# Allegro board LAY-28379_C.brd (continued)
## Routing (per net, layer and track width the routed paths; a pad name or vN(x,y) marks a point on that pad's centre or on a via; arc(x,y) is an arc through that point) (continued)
P3V3: length 201.8
  TOP w0.254: R26.1 63.41,36.7 63.41,36.21 63.41,36.2 v1(63.41,35.98)
  TOP w0.305: U12.1 v1(39.08,31.97) ; U12.8 v1(43.57,34.09)
  TOP w0.381: 23.77,18.45 J18.2 24.71,17.51 ; 28.41,6.81 C48.1 ; C48.1 29.05,7.57 ; C48.1 28.41,8.33 ; 34.51,2.57 J3.8 ; J3.8 35.52,3.58 ; J3.8 36.54,2.57 ; 29.43,2.57 J3.4 ; J3.4 30.44,3.58 ; J3.4 31.46,2.57 ; 18.84,9.84 J15.1 17.9,10.78
  TOP w0.508: v1(16.6,42.95) 18.81,42.95 19.63,43.77 23.35,43.77 SH3.1 24.79,44.63 v1(25.19,45.03) ; R17.1 v1(60.95,39.75)
  TOP w0.635: v1(51.88,7.44) R78.1 ; J20.1 22.88,9.84 23.13,10.08 24.02,10.08
  INT_1 w0.508: v1(25.19,45.03) 25.64,44.58 25.74,44.58 25.79,44.53 28.39,44.53 29.43,43.49 29.43,42.92 30.23,42.13 32.62,42.13 32.66,42.16 v1(33.29,42.16)
  INT_1 w0.635: v1(10.67,40.36) 10.67,38.82 12,37.49 v1(12,23.47)
  BOTTOM w0.152: TP534.1 v1(29.6,9.42)
  BOTTOM w0.254: v1(33.29,42.16) 32.89,41.76 SH500.2
  BOTTOM w0.508: J9.1 38.44,29.72 39.1,30.38 39.1,31.94 v1(39.08,31.97) 40.81,31.97 42.94,34.09 v1(43.57,34.09) 43.57,34.87 C510.1 ; v1(16.6,42.95) 16.07,43.48 14.01,43.48 12.08,41.55 SH502.2 ; v1(12,23.47) 12.51,22.96 20.83,22.96 23.7,20.09 J18.2 ; R509.1 60.28,24.26 R508.1 ; v1(63.41,35.98) 63.41,37 61.61,38.81 61.61,39.09 v1(60.95,39.75) 59.7,38.51 52.39,38.51 51.13,39.77 v1(48.04,39.77) 48.04,42.92 45.21,45.74 34.82,45.74 33.7,46.86 29.38,46.86 27.55,45.03 v1(25.19,45.03)
  BOTTOM w0.635: SH502.2 11.25,39.78 v1(10.67,40.36) ; v1(51.88,7.44) 51.18,7.44 50.83,7.09 v1(30.49,7.09) SH503.2 ; J21.1 20.84,7.92 21.6,8.69 22.11,8.69 22.86,9.44 J20.1 ; v1(48.04,39.77) 46.75,38.48 46.75,36.75 44.55,34.55 44.55,34.46 44.18,34.09 v1(43.57,34.09) 43.57,33.55 44.28,32.84 44.28,32.03 44.64,31.67 J8.1 47.58,30.9 49.45,30.9 50.94,32.38 57.59,32.38 60.32,29.66 R508.1
P3V3_BATT: length 31.8
  TOP w0.508: C43.1 10.57,18.4 ; C43.1 9.94,19.16 ; C43.1 9.94,17.64 ; 16.64,14.57 J27.2 ; J27.2 15.7,15.51 ; J27.2 16.64,16.45 ; 9.92,15.75 11.35,15.75 ; 9.92,15.75 9.92,14.31 ; 9.92,15.75 9.92,17.18 ; 9.92,15.75 8.48,15.75
  INT_1 w0.762: 9.92,15.75 BT500.1
P3V3_BRD: length 79.6
  TOP w0.254: U9.14 v1(50.39,36.34) ; v1(52.87,31.12) 53.42,31.66 U9.1
  TOP w0.508: U4.6 R22.2 C6.1 45.89,39.78 v1(45.97,39.69) 46.78,39.69 48.17,38.3 v1(48.17,37.24) ; v1(59.5,34.32) 60.13,34.32 R29.1 ; R513.1 55.08,43.08 v1(55.64,43.64) 55,43.64 54.99,43.62 54.38,43.62 R13.1 R510.1
  TOP w0.635: R20.1 34.12,39.42 v1(33.52,39.42) ; R20.1 33.79,40.46 R16.1 ; R20.1 R24.1
  INT_1 w0.508: J8.2 47.28,33.67 48.45,34.85 48.45,35.65 49.38,36.58 50.15,36.58 v1(50.39,36.34) 51.04,35.69 51.04,33.86 52.87,32.03 v1(52.87,31.12) ; v1(59.5,34.32) 58.28,34.32 57.77,34.82 57.77,42.14 56.27,43.64 v1(55.64,43.64)
  BOTTOM w0.508: v1(59.5,34.32) 58.64,33.45 53.28,33.45 v1(50.39,36.34) 50.39,37.43 C507.1 C508.1 48.86,37.24 v1(48.17,37.24) ; R507.1 C519.1 50.08,28.6 51.35,29.87 51.35,30.33 52.13,31.12 v1(52.87,31.12)
  BOTTOM w0.635: v1(33.52,39.42) 34.32,38.62 44.9,38.62 v1(45.97,39.69)
P3V3_LED: length 105.5
  TOP w0.508: v1(63.76,10.01) 63.76,10.48 63.09,11.15 LED5.A ; v1(25.29,5.51) 24.09,5.51 R82.1
  TOP w0.635: v1(25.29,5.51) 26.05,5.51 26.38,5.84 v1(26.38,6.53) 25.92,6.53 TP544.1 ; v1(61.25,23.29) LED4.A LED3.A LED2.A LED1.A
  INT_1 w0.508: v1(41.91,23.24) 41.91,19.42 43.73,17.6 43.73,15.39 49.37,9.75 v1(50.19,9.75) ; v1(63.76,10.01) 63.76,9.14 63.28,8.66 63.28,7.24 62.69,6.65 v1(54.02,6.65)
  INT_1 w0.635: v1(26.38,6.53) 27.08,6.53 27.33,6.27 52.94,6.27 53.32,6.65 v1(54.02,6.65)
  BOTTOM w0.381: C49.1 v1(25.29,5.51)
  BOTTOM w0.508: v1(50.19,9.75) 51.81,9.75 54.02,7.54 v1(54.02,6.65) ; v1(41.91,23.24) 42.76,24.09 46.38,24.09 47.64,25.35 50.23,25.35 51.01,26.12 55.73,26.12 57.74,24.1 57.74,22.11 58.6,21.26 60.79,21.26 61.25,21.72 v1(61.25,23.29)
  BOTTOM w0.635: SH503.1 26.94,7.09 v1(26.38,6.53)
P3V3_LED_PWR: length 4.5
  TOP w0.635: LED6.A v1(19.25,7.39)
  BOTTOM w0.635: J20.2 20.09,9.84 19.25,9 v1(19.25,7.39)
P3V3_SDA: length 143.3
  TOP w0.305: v1(15.99,36.93) 16.34,36.93 16.62,37.2 U7.7 ; U8.7 29.33,35.62 v1(29.17,35.46) ; U14.1 v1(29.41,29.77) ; U11.5 23.08,34.03 ; U7.11 v1(18.72,35.22) ; U13.1 v1(29.31,32.69) ; U16.1 v1(29.59,23.44) ; U7.1 v1(17.07,40.86) ; U15.1 v1(29.47,26.57) ; v1(28.94,40.82) 29.27,40.82 29.57,40.52 U5.1
  TOP w0.381: 23.08,34.03 v1(23.05,34.05)
  TOP w0.508: R33.1 v1(16.68,34.34) ; R59.1 v1(32.19,26.44) ; R34.2 v1(24.65,34.14) ; R38.1 20.51,31.42 v1(20.46,31.47) ; R37.1 v1(32.04,32.56) ; J11.1 C31.1 26.53,22.05 27.93,23.44 v1(29.59,23.44) ; R49.1 v1(32.14,29.64) ; R64.1 v1(32.37,23.32) ; R63.1 v1(21.02,25.58) ; v1(17.07,40.86) 17.09,40.88 17.09,41.28 15.59,42.77 v1(11.82,42.77) ; v1(28.94,40.82) 26.88,42.88 R10.1 ; 29.27,40.82 29.68,40.82 30.07,41.21 30.88,41.21 31.48,40.61 R19.1 v1(32.37,40.41)
  INT_1 w0.508: v1(32.37,40.41) 32.37,39.5 32.04,39.17 v1(32.04,32.56) ; v1(11.82,42.77) 10.9,41.85 7.62,41.85 5.55,43.92 v1(5.55,46.38) ; v1(32.14,29.64) 32.14,26.49 v1(32.19,26.44) 32.19,23.5 v1(32.37,23.32) ; v1(15.99,36.93) 17.07,38.01 v1(17.07,40.86) ; v1(21.02,25.58) 21.02,30.91 v1(20.46,31.47) ; v1(29.59,23.44) 29.47,23.57 v1(29.47,26.57) 29.47,29.72 v1(29.41,29.77) 29.31,29.87 v1(29.31,32.69) 29.17,32.83 v1(29.17,35.46) 29.17,38.28 29.57,38.67 29.57,40.52 29.27,40.82 v1(28.94,40.82) ; v1(23.05,34.05) 23.93,34.05 24.02,34.14 v1(24.65,34.14) ; v1(7.58,48.46) 7.58,48.11 5.85,46.38 v1(5.55,46.38) ; v1(5.55,46.38) v1(3.8,48.13)
  BOTTOM w0.203: v1(7.58,48.46) 7.27,48.78 U500.1
  BOTTOM w0.508: SH501.1 13.45,40.44 13.96,40.94 C502.1 14.9,40.92 C504.1 17.01,40.92 v1(17.07,40.86) 17.82,40.11 28.23,40.11 v1(28.94,40.82) 29.56,40.2 C505.1 ; C521.1 29.47,27.24 v1(29.47,26.57) ; v1(29.31,32.69) 29.31,33.36 C516.1 ; 8.39,48.46 v1(7.58,48.46) ; v1(29.59,23.44) 29.59,24.12 C523.1 ; R503.1 5.91,46.74 v1(5.55,46.38) ; C518.1 29.39,29.74 v1(29.41,29.77) ; v1(29.17,35.46) C514.1 ; C513.1 23.08,34.08 v1(23.05,34.05) 21.18,34.05 20.97,34.26 19.37,34.26 18.72,34.91 v1(18.72,35.22) 18.72,35.88 C509.1 v1(15.99,36.93) 15.99,35.03 v1(16.68,34.34) 19.55,31.47 v1(20.46,31.47) ; R501.2 v1(3.8,48.13) ; v1(32.04,32.56) 32.04,32.21 32.75,31.5 32.75,30.25 v1(32.14,29.64)
P3V3_VREG: length 14.8
  TOP w0.508: 13.11,20.12 D7.A ; D7.A 12.46,21.01 ; D7.A 13.76,21.01 ; D7.A 13.11,21.9 ; U17.2 4.79,22.79 ; U17.2 4,24.08 ; U17.2 4,21.49 ; U17.2 3.21,22.79 ; U17.4 4,17.88 ; U17.4 1.94,16.58 ; U17.4 6.06,16.58 ; 8.35,21.68 C27.1 ; C27.1 9.12,21.05 ; C27.1 9.88,21.68
P5V0_SDA_USB_CONN_VBUS: length 5.5
  TOP w0.406: J6.1 5.59,40.97 U6.1
  TOP w0.508: L1.1 8.18,39.42 v1(8.17,39.44) U6.1
P5V_LDO_OUT: length 7.3
  TOP w0.508: 3.5,3.48 J26.3 ; J26.3 4.46,2.53 ; J26.3 4.46,4.43 ; 3.53,5.37 D10.A ; D10.A 4.42,6.02 ; D10.A 3.53,6.66 ; D10.A 2.64,6.02 ; 1.47,5.38 C53.1 2.24,6.01
P5V_SDA: length 35.1
  TOP w0.152: C13.1 12.46,36.86 ; C13.1 11.82,36.09 ; C13.1 12.46,35.33 ; 11.91,34.4 U10.1 12.71,34.9 ; 10.76,34.47 C21.1 ; C21.1 11.26,34.98 ; C21.1 11.77,34.47 ; 11.19,31.06 R40.1 11.7,30.56
  TOP w0.254: 16.27,37.49 16.48,37.71 U7.6
  TOP w0.305: 16.27,37.49 15.1,37.49 v1(14.95,37.34)
  TOP w0.508: L1.2 C3.1 11.75,38.79 ; v1(14.95,37.34) 14.91,37.34 14.63,37.62 12.93,37.62 ; v1(17.26,44.48) 17.23,44.48 16.4,43.64 v1(13.19,43.64) ; R46.1 v1(20.28,30.48)
  INT_1 w0.508: v1(13.19,43.64) 13.19,42.71 14.95,40.95 v1(14.95,37.34)
  BOTTOM w0.508: v1(20.28,30.48) v1(10.78,30.48) ; R504.1 v1(17.26,44.48)
P5V_SDA_PSW: length 11.7
  TOP w0.508: U10.6 v1(15.21,35.26)
  TOP w0.635: D3.A 6.51,34.39 D4.A v1(9.03,34.36)
  BOTTOM w0.635: v1(15.21,35.26) 14.31,34.36 v1(9.03,34.36)
P5V_USB: length 112.5
  TOP w0.254: U12.14 v1(40.12,34.08)
  TOP w0.508: 6.03,31.81 D4.C 6.92,30.52 ; D5.A 5.38,31.45 ; D5.A 4.74,30.56 ; D5.A 4.74,32.33 ; D10.C v1(3.53,10.1)
  INT_1 w0.635: v1(3.53,10.1) 3.53,12.81 5.73,15.01 v1(5.73,30.51)
  BOTTOM w0.508: v1(3.53,10.1) 3.53,7.47 4.6,6.4 18.08,6.4 23.56,0.91 36.41,0.91 J3.10 ; v1(5.73,30.51) 6.67,29.57 11.7,29.57 12.71,28.55 20.26,28.55 21.38,29.67 24.55,29.67 26.56,31.67 26.56,35.34 27.06,35.85 28.63,35.85 30.95,38.18 31.97,38.18 33.92,36.22 39.45,36.22 40.12,35.55 C512.1 40.12,34.09 v1(40.12,34.08)
VDD_1P8: length 14.7
  TOP w0.279: 47.95,19.16 46.73,17.95 46.26,17.95 46.25,17.96 46.04,17.96
  TOP w0.508: 46.04,17.96 v1(44.56,17.96)
  INT_1 w0.635: v1(38.95,14.76) 38.95,13.46 38.05,12.56 J22.5
  BOTTOM w0.635: v1(38.95,14.76) 40.3,14.76 42.99,17.45 44.05,17.45 v1(44.56,17.96)
VDD_1P8F: length 12.9
  TOP w0.279: U18.27 52.69,16.68 v1(52.69,16.99) 52.7,17 53.09,17 53.39,16.7 U18.28
  TOP w0.635: L5.2 C55.1 44.89,17.2 v1(45.2,16.89)
  INT_1 w0.508: v1(45.2,16.89) 45.91,16.89 47.03,18.01 48.81,18.01 50.05,16.76 51.83,16.76 52.06,16.99 v1(52.69,16.99)
VDD_1P45: length 9.9
  TOP w0.279: U18.15 46.61,17.12 46.52,17.12
  TOP w0.508: v1(45.13,15.73) 46.52,17.12
  TOP w0.635: v1(42.66,14.73) 42.47,14.73 41.69,13.96 C45.1 L6.1
  BOTTOM w0.635: v1(45.13,15.73) 44.13,14.73 v1(42.66,14.73)
VDD_1P45F: length 38.1
  TOP w0.254: U18.32 54.18,18.73 54.18,19.16 v1(54.47,19.45) 54.58,19.56 55.47,19.56 U18.35 ; v1(53.63,18.58) U18.31
  TOP w0.635: v1(41.36,11.3) 41.69,11.63 C54.1 41.69,12.42 42.05,12.78 L6.2
  INT_1 w0.635: J22.4 35.83,9.45 37.93,9.45 38.87,10.39 40.7,10.39 41.36,11.05 v1(41.36,11.3)
  BOTTOM w0.254: 53.33,18.73 C527.1 ; C527.1 53.83,19.23 ; C527.1 53.75,18.81 ; C527.1 53.75,19.66 ; 53.84,19.8 C526.1 ; C526.1 54.69,19.8 ; C526.1 54.26,19.71 ; 53.13,18.52 C525.1 53.04,18.09
  BOTTOM w0.635: 53.18,17.95 53.56,17.57 53.56,13.3 52.85,12.6 50.84,12.6 50.15,11.91 47.92,11.91 47.69,12.14 42.2,12.14 v1(41.36,11.3)
ADC0_SE0/BATTERY_MONITORING: length 7.3
  TOP w0.152: SH26.1 R78.2 50.86,11.24 v1(50.79,11.31) 50.46,11.64 50.46,14.61 U18.24
ADC0_SE1/POT: length 68.1
  TOP w0.152: v1(8.62,8.13) 8.3,8.45 8.3,9.74 C32.1 7.7,10.34 5.85,10.34 ; SH27.1 v1(53.38,9.68) 53.38,9.95 51.49,11.84 51.49,14.78 U18.25
  INT_1 w0.152: v1(53.38,9.68) 53.7,9.35 53.81,9.35 54.62,8.55 56.46,8.55 56.76,8.25 56.76,7.7 56.53,7.47 53.58,7.47 52.84,8.2 51.45,8.2 50.15,6.91 31.51,6.91 30.87,7.54 24.27,7.54 23.25,6.53 21.73,6.53 21.48,6.78 9.97,6.78 v1(8.62,8.13)
  BOTTOM w0.152: TP532.1 53.38,9.68 v1(53.38,9.68)
BUZZER: length 32.3
  TOP w0.152: v1(44.48,30.81) 44.48,28.56 43.9,27.99 SH22.2 v1(43.57,23.24) ; SH10.1 R12.1 v1(44.48,41.15) ; U18.19 v1(50.28,17.96)
  INT_1 w0.152: v1(44.48,30.81) v1(44.48,41.15) ; v1(43.57,23.24) 45.38,23.24 46.7,21.92 46.7,20.83 49.56,17.96 v1(50.28,17.96)
BYP_FXOS8700CQ: length 4.7
  TOP w0.152: U9.2 v1(53.92,30.93) 53.92,30.82 C22.1
CMT: length 54.8
  TOP w0.152: v1(57.9,11.25) 57.9,10.39 57.19,9.68 SH29.1 57.16,8.89 56.38,8.89 v1(55.58,8.09) ; U18.17 v1(49.57,18.67)
  INT_1 w0.152: v1(55.58,8.09) 55.12,8.09 54.98,7.95 53.71,7.95 52.97,8.69 51.35,8.69 49.95,7.29 31.7,7.29 31.06,7.92 25.92,7.92 v1(25.29,8.56) ; v1(57.9,11.25) 56.74,11.25 53.15,14.84 53.15,17.18 52.88,17.45 51.47,17.45 50.25,18.67 v1(49.57,18.67)
  BOTTOM w0.152: R80.1 23.25,5.51 25.16,7.42 TP535.1 v1(25.29,8.56)
COM: length 20.1
  TOP w0.152: v1(61.02,9.8) 60.36,9.14 SH31.1 ; v1(48.15,17.27) 48.15,17.93 48.26,18.05 48.26,18.06 U18.16
  INT_1 w0.152: v1(48.15,17.27) 48.15,15.98 48.3,15.82 50.43,15.82 53.78,12.47 54.56,12.47 56.56,10.47 60.36,10.47 v1(61.02,9.8)
  BOTTOM w0.152: R511.2 61,9.83 v1(61.02,9.8)
CRST_FXOS8700CQ: length 4
  TOP w0.152: C11.1 59.3,37.18 v1(58.45,36.34) U9.8
D7: length 10.5
  TOP w0.152: v1(42.35,43.05) 42.35,43.77 R5.1 ; v1(42.35,35.33) U12.10
  INT_1 w0.152: v1(42.35,43.05) v1(42.35,35.33)
D8: length 11.6
  TOP w0.152: U12.11 v1(41.85,36.17) ; R4.1 41.23,44.63 v1(40.46,43.86)
  INT_1 w0.152: v1(40.46,43.86) 41.85,42.47 v1(41.85,36.17)
D9: length 11.6
  TOP w0.152: R3.1 38.6,44.03 v1(38.6,42.98) ; U12.12 v1(41.35,35.36)
  INT_1 w0.152: v1(41.35,35.36) 41.35,40.23 v1(38.6,42.98)
D10: length 13.2
  TOP w0.152: v1(37.63,42.9) 36.28,42.9 36.1,43.09 36.1,43.77 36.1,44.08 R8.1 ; v1(40.85,36.14) U12.13
  INT_1 w0.152: v1(37.63,42.9) 40.85,39.68 v1(40.85,36.14)
DCDC_CFG: length 15
  TOP w0.279: v1(47.56,21.92) 48.16,21.92 U18.9
  BOTTOM w0.635: v1(47.56,21.92) 46.06,20.42 42.61,20.42 39.69,17.51 J17.1 J17.3
DCDC_LP: length 16.6
  TOP w0.279: L3.1 46.77,21.9 47.95,20.72
  TOP w0.508: L3.1 40.98,21.9 37.91,18.82 35,18.82 J17.5
ELEC_IN1: length 45.7
  TOP w0.152: SH15.1 v1(58.45,43.8) ; U18.4 50.42,23.2 49.98,23.64 49.29,23.64 v1(48.92,23.27) ; v1(59.96,32.18) 59.96,31.47 61.73,31.47 62.59,30.61 62.59,29.28 63.62,28.25 v2(63.65,28.25) 62.41,27.02 62.41,22.91 62.02,22.52 60.24,22.52 58.81,21.1 v1(58.81,20.45)
  INT_1 w0.152: v1(59.96,32.18) 59.96,38.2 59.37,38.79 59.37,42.35 58.45,43.28 v1(58.45,43.8) ; v1(48.92,23.27) 48.92,21.39 49.68,20.63 50.43,20.63 50.95,20.11 51.38,20.11 51.64,20.37 52.18,20.37 52.44,20.11 52.79,20.11 53.05,20.37 55.51,20.37 56.39,19.5 57.86,19.5 v1(58.81,20.45)
ELEC_IN2: length 48.2
  TOP w0.152: U18.5 49.79,23.12 49.43,23.12 49.08,22.77 48.61,22.77 v1(48.16,23.22) ; v1(59.95,20.33) 60.82,20.33 TVS2.1 62.16,20.65 v2(63.64,22.13) ; SH14.1 57.58,44.33 v1(57.58,43.89)
  INT_1 w0.152: v1(57.58,43.89) 57.58,43.53 58.86,42.25 58.86,38.48 59.45,37.89 v1(59.45,36.53) ; v1(59.95,20.33) 58.62,18.99 56.15,18.99 55.19,19.95 54.21,19.95 53.62,19.36 53.14,19.36 52.83,19.68 52.45,19.68 52.16,19.39 51.69,19.39 51.42,19.66 50.98,19.66 50.65,19.33 50,19.33 48.42,20.91 48.42,22.96 v1(48.16,23.22)
  BOTTOM w0.152: v2(63.64,22.13) 61.52,24.25 61.52,32.08 60.5,33.11 60.5,35.48 v1(59.45,36.53)
EXTAL_32M: length 6.8
  TOP w0.152: U18.29 53.75,17.04 54.14,16.65 54.14,15.57 C44.1 52.91,14.34 52.91,12.39 Y1.1
I2C1_SCL: length 43.5
  TOP w0.152: v1(58.76,22.28) 56.71,22.28 56.24,21.82 56.24,21.09 U18.38 ; R54.2 64.21,7.65 63.92,7.94 v1(63.92,8.39) ; R42.2 58.71,32.66 60.27,32.66 60.93,32 v1(62.57,32)
  INT_1 w0.152: v1(62.57,32) 62.41,31.84 62.41,28.36 58.78,24.73 58.78,22.31 v1(58.76,22.28) 60.41,20.63 60.41,19.39 60.11,19.09 60.11,19.09 60.09,19.07 60.09,12.56 61.73,10.92 62.63,10.92 62.64,10.92 63.61,10.92 64.02,10.5 64.03,10.5 64.55,9.98 64.55,9.03 v1(63.92,8.39)
  BOTTOM w0.152: R509.2 58.53,22.83 58.76,22.6 v1(58.76,22.28) ; TP20.1 63.7,32 v1(62.57,32)
I2C1_SDA: length 41.1
  TOP w0.152: U18.39 55.93,21.49 55.93,22.79 56.42,23.28 v1(59.37,23.28) ; R45.1 63.57,9.17 64.22,9.82 64.22,10.95 v1(64.21,10.96) ; R30.2 59.86,33.55 60.83,32.58 63.37,32.58 63.46,32.66 v1(63.92,32.66)
  INT_1 w0.152: v1(63.92,32.66) 63.92,32.11 63.02,31.21 63.02,27.57 59.37,23.93 v1(59.37,23.28) 61.03,21.63 61.03,14.15 63.89,11.29 63.89,11.28 v1(64.21,10.96)
  BOTTOM w0.152: TP19.1 64.4,32.66 v1(63.92,32.66) ; v1(59.37,23.28) R508.2
I2C_SCL_FXOS8700CQ: length 4.9
  TOP w0.152: U9.4 v1(54.92,30.93) 55.06,31.06 R42.1
I2C_SDA_FXOS8700CQ: length 3.7
  TOP w0.152: R30.1 58.84,34.95 v1(58.45,35.34) U9.6
INT1_COMBO: length 37.6
  TOP w0.152: v1(45.02,22.71) v1(45.02,33.35) ; R510.2 52.18,43.26 51.3,43.26 v1(50.81,43.74) R7.2 SH11.1 ; v1(46.86,16.37) 46.9,16.33 46.9,16.2 R68.2
  INT_1 w0.152: v1(45.02,22.71) 45.02,17.78 44.74,17.5 44.74,16.7 45.07,16.37 v1(46.86,16.37) ; v1(45.02,33.35) 48.6,36.93 48.6,41.53 v1(50.81,43.74)
INT1_COMBO_R: length 10.2
  TOP w0.152: U9.11 v1(54.42,39.89) ; R7.1 51.57,44.88 51.57,44.2 51.6,44.17 v1(51.6,43.71)
  INT_1 w0.152: v1(51.6,43.71) 52.11,43.21 52.34,43.21 54.42,41.12 v1(54.42,39.89)
INT2_COMBO: length 4.4
  TOP w0.152: R513.2 56.46,42.56 56.62,42.56 TP14.1 58.33,40.79 R18.2
INT2_COMBO_R: length 3.9
  TOP w0.152: U9.9 v1(55.42,39.89) 56.07,40.54 R18.1
J_VDD_1P8F: length 49.3
  TOP w0.254: v1(54.14,23.61) 54.14,23.23 U18.44 ; U18.20 v1(49.31,16.28)
  TOP w0.635: v1(41.49,14.83) 41.49,15.56 41.58,15.65 L5.1 C39.1
  BOTTOM w0.635: 38.37,13.89 38.37,10.97 37.95,10.56 J22.3 ; 38.37,13.89 25.54,13.89 J18.4 ; 38.37,13.89 40.55,13.89 v1(41.49,14.83) 41.9,14.43 41.9,14.42 42.34,13.97 42.35,13.97 42.53,13.79 C529.1 46.84,13.79 46.84,13.79 47.68,14.63 C530.1 47.68,14.66 C528.1 48.4,15.37 v1(49.31,16.28) 49.25,16.35 49.25,16.98 48.88,17.35 48.88,19.27 51.34,21.73 51.34,22.8 C524.1 52.19,23.65 54.1,23.65 v1(54.14,23.61)
KW40_SWD_CLK: length 36
  TOP w0.152: 51.13,23.9 50.39,24.64 v1(49.65,24.64) ; J12.2 39.22,25.32 v1(39.67,24.87) ; SH8.1 37.92,44.11 37.17,43.36 36.69,43.36 v1(36.66,43.38)
  INT_1 w0.152: v1(49.65,24.64) 44.88,24.64 44.65,24.87 v1(39.67,24.87) 39.56,24.98 39.56,39.65 36.66,42.54 v1(36.66,43.38)
LVLRST_EN: length 1.1
  BOTTOM w0.152: U500.5 R501.1
MIC2005_CSLEW: length 3.7
  TOP w0.152: C13.2 13.98,33.71 14.24,33.45 U10.5
Net_221: length 3.6
  TOP w0.152: 53.14,35.84 v1(49.59,35.84)
P5-9V_VIN: length 79.6
  TOP w0.508: C50.1 8.67,5.82 ; C50.1 7.91,5.18 ; C50.1 7.15,5.82 ; 9.54,2.53 J26.1 ; J26.1 8.58,3.48 ; J26.1 10.49,3.48 ; J26.1 9.54,4.43 ; 8.93,5.82 C51.1 ; C51.1 10.45,5.82 ; C51.1 9.69,5.18 ; 11.47,5.18 C52.1 ; C52.1 10.71,5.82 ; C52.1 12.23,5.82 ; D6.A v1(6.74,28.63)
  INT_1 w0.508: J3.16 43.98,0.86 23.53,0.86 18.12,6.27 12.33,6.27 J26.1 7.94,5.08 7.94,13.13 6.74,14.33 6.74,25.83 7.66,26.75 7.66,27.53 6.74,28.45 v1(6.74,28.63)
P5-9V_VIN_VR: length 48.8
  TOP w0.508: 2.19,30.56 D5.C ; D5.C 2.19,32.33 ; D5.C 0.89,31.45 ; D6.C 2.19,29.52 ; D6.C 2.19,27.74 ; D6.C 0.89,28.63 ; 2.19,33.5 D3.C ; D3.C 2.19,35.28 ; D3.C 0.89,34.39
  INT_1 w0.508: v1(8.14,23.8) 8.14,14.53 8.9,13.77 11.44,13.77 13.6,11.61 25.79,11.61 26.3,12.12 27.44,12.12 27.79,11.77 J33.2
  BOTTOM w0.508: v1(8.14,23.8) 7.76,23.8 5.09,26.47 2.3,26.47 v1(1.51,27.25)
POWER_EN: length 14
  TOP w0.152: R41.1 16.68,31.06 17.39,31.78 v1(17.87,31.78) ; U7.31 v1(18.22,41.64)
  INT_1 w0.152: v1(18.22,41.64) 18.22,41.13 18.72,40.63 18.72,37.45 19.19,36.98 19.19,32.94 18.02,31.78 v1(17.87,31.78)
PSWITCH: length 44.2
  TOP w0.254: U18.8 48.3,22.49 47.3,22.49 v1(46.69,23.1)
  TOP w0.381: v1(19.01,26.62) 16.9,26.62 16.12,27.41 SW5.1
  INT_1 w0.381: J16.5 26.65,19.67 23.53,22.78 19.86,22.78 19.01,23.63 v1(19.01,26.62)
  BOTTOM w0.635: J16.5 J16.3 J16.1 32.21,19.08 39.41,19.08 42.05,21.72 45.3,21.72 v1(46.69,23.1)
PTB16: length 13.3
  TOP w0.152: v1(45.48,14.91) 45.65,14.91 45.73,14.83 45.96,14.83 46.27,14.52 R71.1 ; SH28.1 v1(54.65,9.98)
  INT_1 w0.152: v1(54.65,9.98) 53.89,10.74 52.03,10.74 48.17,14.59 45.8,14.59 v1(45.48,14.91)
PTB16/XTAL_32K: length 5.9
  TOP w0.152: R74.1 47.35,13.39 47.35,13.39 47.9,13.94 47.9,14.16 U18.21
PTB17: length 2.6
  TOP w0.152: SH25.1 49.29,9.19 R76.2
PTB17/EXTAL_32K: length 6.3
  TOP w0.152: R77.1 48.21,12.5 48.21,12.5 49.39,13.67 49.39,14.95 U18.22
PTB18: length 18.2
  TOP w0.152: 51.13,15.98 49.92,14.77 v1(49.92,14.35) ; v1(62.27,9.66) 61.81,9.66 61.63,9.49 SH33.1
  INT_1 w0.152: v1(62.27,9.66) 61.65,9.04 59.86,9.04 59.04,9.86 55.84,9.86 54.13,11.56 53.35,11.56 50.56,14.35 v1(49.92,14.35)
PTC0: length 65.2
  TOP w0.152: U18.36 56.23,19.52 v1(57.15,20.44) ; R62.2 55.9,23.77 v1(55.9,23.76) ; R88.2 v1(19.51,46.19)
  INT_1 w0.152: v1(19.51,46.19) 19.53,46.21 27.26,46.21 27.8,46.75 27.8,46.93 28.07,47.19 33.6,47.19 34.77,46.02 43.65,46.02 44.95,44.73 52.45,44.73 57.24,39.94 57.24,29.06 56.45,28.27 56.45,25.41 55.9,24.85 v1(55.9,23.76)
  BOTTOM w0.152: v1(57.15,20.44) 55.91,21.68 55.91,23.75 v1(55.9,23.76)
PTC1: length 60.5
  TOP w0.152: R87.1 v1(23.32,44.67) ; U18.37 56.84,21 v1(56.84,21.67) ; R57.2 v1(55.23,25.3)
  INT_1 w0.152: v1(23.32,44.67) 24.21,45.56 27.92,45.56 29.25,46.89 33.5,46.89 34.83,45.56 43.32,45.56 44.59,44.3 51.87,44.3 51.87,44.3 52.21,44.3 56.93,39.57 56.93,29.78 55.88,28.73 55.88,25.94 55.62,25.69 55.61,25.68 55.56,25.62 v1(55.23,25.3)
  BOTTOM w0.152: v1(56.84,21.67) 56.84,23.9 55.45,25.3 v1(55.23,25.3)
PTC4: length 45.5
  TOP w0.152: v1(41.64,27.38) SH20.2 R56.2 41.03,24.74 v1(39.48,23.19) ; SH24.1 v1(48.07,9.8) ; R53.2 55.23,27.03 v1(55.21,27) 55.16,27 54.65,26.49 54.65,24.27 55.5,23.41 55.5,21.77 U18.40
  INT_1 w0.152: v1(55.21,27) 54.83,27.38 v1(41.64,27.38) ; v1(39.48,23.19) 39.48,20.22 41.75,17.95 41.75,16.18 46.14,11.78 46.14,11.06 47.4,9.8 v1(48.07,9.8)
PTC5: length 63.3
  TOP w0.152: v1(58.34,8.89) 58.91,8.89 58.93,8.92 SH30.1 ; U18.41 55.12,22.09 55.12,23.3 54.24,24.18 54.24,26.6 54.59,26.95 54.59,28.11 v1(55.23,28.75) R48.2 ; R52.2 SH23.2 v1(40.27,27.43) 40.27,26.06 40.59,25.75 40.59,24.95 39.38,23.75 39,23.75 38.7,23.45 v1(38.7,23.45)
  INT_1 w0.152: v1(38.7,23.45) 38.7,18.92 40.83,16.79 40.83,14.35 46.13,9.05 50.72,9.05 51.8,10.13 53.59,10.13 54.83,8.89 v1(58.34,8.89) ; v1(55.23,28.75) 50.36,28.75 49.67,29.44 45.68,29.44 44.68,28.44 41.28,28.44 v1(40.27,27.43)
RF_50: length 8.2
  TOP w0.457: C40.1 L4.1 C33.1 61.33,14.51
RF_ANT: length 3.8
  TOP w0.457: C40.2 ANT1.1 74.36,14.51
RF_N: length 2.2
  TOP w0.216: U18.33 55.27,18.46 56.45,17.27 R70.1
RF_P: length 2.2
  TOP w0.216: R69.1 56.71,17.53 55.51,18.73 U18.34
RF_SMA: length 35.4
  TOP w0.457: J5.1 78.93,44.19 75.78,44.19 arc(71.38,42.37) 69.56,37.97 C34.2
RST_FXOS8700CQ: length 5.7
  TOP w0.152: R32.1 50.39,34.96 v1(50.39,35.34) U9.16
  BOTTOM w0.152: v1(50.39,35.34) 50.39,34.7 R506.1
RST_TGTMCU_B: length 136.9
  TOP w0.152: U18.3 50.77,23.55 50.14,24.18 49.45,24.18 48.73,24.89 48.73,26.47 49.75,27.48 49.75,32.74 R32.2 49.06,32.77 47.03,34.8 44.28,34.8 42.46,36.63 40.25,36.63 39.31,35.69 36.77,35.69 J9.10 v1(33.36,34.8) ; D1.C 3.99,51.87 v1(6.52,51.87)
  INT_1 w0.152: v1(22.87,6.02) 22.87,4.75 23.76,3.86 31.69,3.86 J3.6 ; v1(25.29,12.24) 23.51,14.02 21.34,14.02 20.17,15.19 20.17,18.38 17.16,21.4 17.16,31.45 15.94,32.66 15.94,35.28 12.43,38.79 12.43,43.42 J24.3 11.86,45.87 16.6,45.87 20.43,42.04 29.37,42.04 30.07,41.34 32.39,41.34 32.91,40.82 32.91,37.46 33.36,37.01 v1(33.36,34.8)
  BOTTOM w0.152: J24.3 10.91,44.94 R502.2 10.35,47.78 10.35,51 9.49,51.87 v1(6.52,51.87) R500.2 U500.7 ; v1(22.87,6.02) 23.25,6.02 24.14,6.91 24.14,11.3 24.57,11.73 24.78,11.73 v1(25.29,12.24)
SA0_FXOS8700CQ: length 6.3
  TOP w0.152: SH19.1 R29.2 U9.7
SA1_FXOS8700CQ: length 6
  TOP w0.152: R13.2 54.14,41.85 54.26,41.73 SH18.1 54.92,40.76 v1(54.92,40.75) U9.10
SDA_CTS_EN: length 2.1
  TOP w0.152: U13.5 R37.2 R39.1
SDA_EXTAL: length 5.1
  TOP w0.152: X1.3 24.42,35.62 C15.1 22.85,36.7 U7.17
SDA_JTAG_TCLK: length 12.8
  TOP w0.152: U7.12 19.22,28.78 23.06,24.94 J11.4
SDA_JTAG_TDI: length 10
  TOP w0.152: v1(19.72,35.1) U7.13
  INT_1 w0.152: J11.8 22.36,28.32 22.36,30.38 20.92,31.83 20.92,33.91 v1(19.72,35.1)
SDA_JTAG_TDO: length 11.4
  TOP w0.152: U7.14 20.22,34.84 19.82,34.44 19.82,29.59 J11.6
SDA_JTAG_TMS: length 15.9
  TOP w0.152: J11.2 R63.2 v1(20.15,23.67) ; U7.15 20.72,34.78 20.33,34.39 v1(20.33,33.55)
  INT_1 w0.152: v1(20.15,23.67) 20.15,29.72 19.82,30.05 19.82,33.05 v1(20.33,33.55)
SDA_LED: length 3.4
  TOP w0.152: D2.C 20.61,42.88 v1(20.49,42.75) 19.22,41.48 U7.29
SDA_LED_R: length 1.4
  TOP w0.152: R10.2 D2.A
SDA_RST: length 14.7
  TOP w0.152: U7.19 21.88,37.69 22.65,37.69 v1(22.68,37.67) ; R47.1 v1(23.2,30.48) ; v1(23.2,30.48) 23.2,28.75 ; v1(23.2,30.48) R46.2
  INT_1 w0.152: v1(23.2,30.48) 21.5,32.18 21.5,34.77 22.68,35.95 v1(22.68,37.67)
  BOTTOM w0.152: TP524.1 22.75,30.48 v1(23.2,30.48)
SDA_RST_LED: length 1.1
  TOP w0.152: D1.A R1.2
SDA_RST_TGTMCU_B: length 10.3
  TOP w0.152: U7.21 v1(22.67,38.71)
  INT_1 w0.152: J25.2 15.8,44.79 21.88,38.71 22.67,38.71 v1(22.67,38.71)
SDA_RST_TGTMCU_J_B: length 14.2
  TOP w0.152: J24.1 7.87,43.98 12.88,43.98 J25.1
  BOTTOM w0.152: R503.2 J24.1 ; R503.2 6.92,47.22 U500.2 ; R503.2 R502.1
SDA_RTS_EN: length 2.1
  TOP w0.152: R51.1 R49.2 U14.5
SDA_RX_EN: length 2.1
  TOP w0.152: U5.5 R19.2 R23.1
SDA_SPI0_SCK: length 27
  TOP w0.152: U7.26 20.72,41.26 20.94,41.48 21.68,41.48 21.83,41.33 v1(24.57,41.33) ; v1(28.05,21.79) 28.06,21.8 U16.3
  INT_1 w0.152: v1(24.57,41.33) 24.7,41.2 24.7,36.02 26.15,34.57 26.15,30.2 26.73,29.62 26.73,23.11 v1(28.05,21.79)
SDA_SPI0_SIN: length 13.4
  TOP w0.152: U8.5 28.85,37.25 28.41,37.69 v1(28.41,37.97) ; v1(26.35,41.48) 25.74,42.09 20.54,42.09 19.72,41.27 U7.28
  INT_1 w0.152: v1(28.41,37.97) 26.35,40.03 v1(26.35,41.48)
SDA_SPI0_SOUT: length 25.4
  TOP w0.152: U7.27 20.22,41.26 20.74,41.78 25.01,41.78 v1(25.36,41.43) ; v1(27.32,24.93) U15.3
  INT_1 w0.152: v1(25.36,41.43) 25.36,36.37 26.68,35.05 26.68,30.45 27.32,29.82 v1(27.32,24.93)
SDA_SWD_EN: length 23.7
  TOP w0.152: R66.1 v1(33.49,20.4) ; U11.6 22.58,33.42 22.42,33.57 22.14,33.57 21.99,33.42 v1(21.99,33.12) ; R50.1 v1(26.07,29.08)
  INT_1 w0.152: v1(21.99,33.12) 22.31,32.79 22.67,32.79 26.07,29.39 v1(26.07,29.08) 26.07,22.43 28.11,20.4 v1(33.49,20.4)
SDA_SWD_EN_B: length 1.5
  TOP w0.152: R31.2 21.22,34.55 U7.16
SDA_SWD_EN_B_R: length 2.7
  TOP w0.152: R31.1 21.25,33.5 R38.2 21.77,32.44 21.84,32.51 22.47,32.51 22.58,32.4 U11.1
SDA_SWD_EN_R: length 3.1
  TOP w0.152: U16.5 R64.2 R65.1 R66.2
SDA_SWD_OE: length 24.6
  TOP w0.152: v1(33.95,24.97) 33.95,24.71 33.69,24.46 R61.1 ; v1(28.56,30.56) 27.61,30.56 26.76,31.4 R36.1 26.76,34.01 26.12,34.65 24.36,34.65 24.13,34.41 24.13,34.02 23.58,33.47 U11.4
  INT_1 w0.152: v1(33.95,24.97) 33.01,24.03 33.01,23.19 32.47,22.66 29.43,22.66 28.26,23.83 28.26,29.06 28.56,29.36 v1(28.56,30.56)
SDA_SWD_OE_B: length 7.1
  TOP w0.152: R35.2 v1(25.64,34.16) ; v1(23.14,38.2) 21.87,38.2 U7.20
  INT_1 w0.152: v1(23.14,38.2) 24.04,37.3 24.04,35.81 25.64,34.21 v1(25.64,34.16)
SDA_SWD_OE_B_R: length 2.1
  TOP w0.152: U11.3 24.01,32.24 24.13,32.36 R34.1 R35.1
SDA_SWD_OE_R: length 3
  TOP w0.152: U15.5 R59.2 R60.1 R61.2
SDA_USB_DN: length 1.7
  TOP w0.254: U7.4 16.46,38.71 16.43,38.73
  TOP w0.292: R25.2 15.86,38.73 16.43,38.73
SDA_USB_DP: length 1.7
  TOP w0.254: 16.43,39.21 U7.3
  TOP w0.292: R21.2 15.88,39.18 16.41,39.18 16.43,39.21
SDA_USB_P5V_SENSE: length 3.8
  TOP w0.152: v1(19.09,42.27) 18.72,41.9 U7.30
  BOTTOM w0.152: R504.2 R505.1 v1(19.09,42.27)
SDA_VOUT33: length 5.3
  TOP w0.305: U7.5 v1(16.27,38.21)
  BOTTOM w0.508: v1(16.27,38.21) 14.98,38.21 C506.1 SH501.2 12.59,38.18 12.08,38.68 SH502.1
SDA_XTAL: length 5
  TOP w0.152: X1.1 24.56,38.02 C10.1 23.04,37.2 U7.18
SPI_CLK: length 46.4
  TOP w0.152: U4.2 v1(35.73,41.05) 35.04,41.05 R16.2 33.96,41.67 28.79,41.67 27.83,42.63 27.83,43.31 27.83,43.31 v1(27.83,43.77) 26.97,44.63 SH4.1 ; v1(52.59,22.62) 52.81,22.62 U18.45
  INT_1 w0.152: v1(35.73,41.05) 35.73,40.51 37.99,38.25 37.99,29.52 38.55,28.96 38.55,24.55 39.38,23.72 49.25,23.72 50.36,22.62 v1(52.59,22.62)
SPI_SIN: length 16.6
  TOP w0.152: U4.8 v1(43.57,42.32) ; J28.2 33.66,43.61 33.78,43.74 R84.2
  INT_1 w0.152: J28.2 33,43.61 33.32,43.93 33.32,44.82 33.59,45.09 34.52,45.09 35.12,44.49 41.89,44.49 43.57,42.81 v1(43.57,42.32)
SPI_SOUT: length 11.9
  TOP w0.152: R83.2 29.03,44.63 29.36,44.96 29.36,45.43 29.54,45.61 J29.1 ; U4.1 v1(35.5,42.32)
  BOTTOM w0.152: v1(35.5,42.32) 35.15,42.66 31.76,42.66 31.49,42.92 31.49,44.71 30.59,45.61 J29.1
SPI_SS: length 41.9
  TOP w0.152: v1(34.91,26.92) 35.32,26.92 35.96,26.29 38.49,26.29 38.98,25.81 39.74,25.81 v1(40.13,25.42) ; U4.4 R24.2 35.5,38.18 v1(35.88,37.8) ; SH7.1 v1(34.19,44.63) ; v1(51.82,24.77) U18.48
  INT_1 w0.152: v1(51.82,24.77) 51.27,24.23 50.77,24.23 49.9,25.1 45.25,25.1 44.93,25.42 v1(40.13,25.42) ; v1(34.91,26.92) 34.91,28.68 33.95,29.64 33.95,35.43 35.88,37.36 v1(35.88,37.8) 35.88,38.61 34.19,40.3 v1(34.19,44.63)
SW1_RST_B: length 5.8
  TOP w0.152: SW6.2 8.9,47.25 C1.1 8.9,44.95 J24.2
SW3: length 43.8
  TOP w0.152: v1(49.76,21.33) 49.76,21.74 U18.7 ; v1(62.46,33.03) 62.43,33.06 SW3.1 62.43,36.2 62.42,36.21 R26.2 C9.1 62.42,38.18 61.53,39.07 59.21,39.07 59.05,39.22 59.05,40.96 55.92,44.09 54.04,44.09 v1(53.51,44.63) SH12.1
  INT_1 w0.152: v1(49.76,21.33) 51.24,21.33 51.65,20.91 52.24,20.91 52.41,21.08 52.83,21.08 53.14,20.77 55.85,20.77 56.65,19.96 57.57,19.96 58.1,20.5 58.1,25.43 61.84,29.16 61.84,32.41 v1(62.46,33.03)
SW4: length 38.7
  TOP w0.152: U18.6 v1(50.31,21.9) ; v1(62.43,39.01) SW4.1 62.43,40.21 62.43,41.33 62.23,41.53 R17.2 C2.1 59.26,41.53 56.16,44.63 v1(55.66,44.63) SH13.1
  INT_1 w0.152: v1(62.43,39.01) 62.42,39 62.42,36.17 61.35,35.1 61.35,30 57.67,26.31 57.67,23.17 55.6,21.1 53.53,21.1 52.73,21.9 v1(50.31,21.9)
  BOTTOM w0.152: TP502.1 v1(55.66,44.63)
SWD_CLK_TGTMCU: length 13.2
  TOP w0.152: J9.4 v1(34.46,30.99)
  INT_1 w0.152: J14.2 36.61,21.62 36.61,23.48 35.57,24.52 J12.1 35.57,28.85 34.46,29.97 v1(34.46,30.99)
SWD_CLK_TGTMCU_BUF: length 8.6
  TOP w0.152: U16.4 30.94,21.8 33.21,19.53 36.52,19.53 J14.1
SWD_DIO_TGTMCU: length 48.1
  TOP w0.152: v1(39.19,43.87) 39.95,44.63 SH9.1 ; U18.1 v1(50.91,24.83) ; SH21.2 v1(42.3,26.87) 41.83,26.4 41.83,24.75 39.66,22.58 38.91,22.58 38.52,22.96 J13.2
  INT_1 w0.152: v1(42.3,26.87) 44.41,26.87 45.89,25.4 50.34,25.4 v1(50.91,24.83) ; v1(39.19,43.87) 35.1,43.87 34.73,43.5 34.73,40.56 36.44,38.86 36.44,36.42 35.04,35.03 35.04,30.56 J9.2 36.57,29.02 36.57,24.7 37.57,23.7 J13.2
SWD_DIO_TGTMCU_BUF: length 22.4
  TOP w0.152: U8.2 v1(31.28,36.75) ; J13.1 34.49,22.96 33.57,23.88 31.92,23.88 30.87,24.93 U15.4
  INT_1 w0.152: v1(31.28,36.75) 31.28,31.72 34.43,28.57 34.43,24.1 J13.1
TC_EXTAL_TP: length 2.2
  TOP w0.152: v1(18.43,33.93) 18.22,34.14 U7.10
TC_XTAL_TP: length 1.4
  TOP w0.152: v1(17.51,34.77) 17.72,34.98 U7.9
TP_2102_A: length 2.6
  BOTTOM w0.152: TP501.1 5.42,47.85 6.26,47.85 6.52,48.11 U500.3
TP_2102_B: length 1.7
  BOTTOM w0.152: U500.6 5.66,49.8 5.19,50.27 TP500.1
UART0_CTS_TGTMCU: length 5.9
  TOP w0.152: R43.2 33.45,30.58 v1(36.07,27.97) R52.1
UART0_RTS_TGTMCU: length 7.6
  TOP w0.152: R56.1 36.21,26.59 35.19,27.61 v1(33.57,27.61) R55.2
UART0_RX_TGTMCU: length 72
  TOP w0.152: R27.2 37.99,37.24 38.57,37.82 44.07,37.82 45.95,35.94 47.66,35.94 49.85,38.13 49.85,43.06 47.94,44.97 v1(47.94,46.42) ; v1(53.9,21.58) 53.9,21.58 U18.42
  INT_1 w0.152: v1(47.94,46.42) 62.07,46.42 J30.2 61.87,44.61 61.87,37.81 60.91,36.84 60.91,31.13 57.28,27.5 57.28,23.43 55.42,21.58 v1(53.9,21.58)
UART0_TX_TGTMCU: length 70.3
  TOP w0.152: v1(59.5,44.46) 59.92,44.46 60.77,43.61 J31.1 ; v1(53.25,22.05) 53.66,22.05 U18.43 ; R28.2 32.58,35.86 32.81,35.63 34.2,35.63 34.94,36.37 38.98,36.37 39.79,37.19 43.13,37.19 44.85,35.46 47.84,35.46 50.27,37.89 50.27,43.12 48.56,44.84 v1(48.56,45.62)
  INT_1 w0.152: v1(53.25,22.05) 55.31,22.05 56.84,23.58 56.84,28.13 60.51,31.8 60.51,41.77 59.78,42.5 59.78,43.47 59.5,43.74 v1(59.5,44.46) 59.18,44.79 59.18,45.08 58.65,45.62 v1(48.56,45.62)
UART1_CTS_TGTMCU_BUF: length 1.3
  TOP w0.152: R43.1 31.08,30.58 30.62,31.04 30.12,31.04 U13.4
UART1_CTS_TGTMCU_R: length 16.2
  TOP w0.152: R36.2 v1(27.77,31.04) 27.78,31.05 U13.3 ; v1(26.73,38.96) 26.73,39.09 26.12,39.71 U7.23
  INT_1 w0.152: v1(26.73,38.96) 26.73,37.26 27.77,36.22 v1(27.77,31.04)
UART1_RTS_TGTMCU_BUF: length 1.3
  TOP w0.152: U14.4 30.22,28.12 30.72,28.12 31.23,27.61 R55.1
UART1_RTS_TGTMCU_R: length 19.4
  TOP w0.152: v1(25.84,39.21) U7.22 ; R50.2 27.88,28.22 v1(27.77,28.12) 29.44,28.12 U14.3
  INT_1 w0.152: v1(25.84,39.21) 25.84,36.98 27.14,35.69 27.14,30.73 27.77,30.1 v1(27.77,28.12)
  BOTTOM w0.152: TP525.1 v1(27.77,28.12)
UART1_RX_TGTMCU_BUF: length 2.9
  TOP w0.152: U5.4 30.92,38.9 R27.1
UART1_RX_TGTMCU_R: length 9.2
  TOP w0.152: U5.3 28.33,38.9 v1(28.08,39.14) 26.37,40.86 U7.25
UART1_TX_TGTMCU_BUF: length 3.5
  TOP w0.152: U8.1 31.49,36.23 31.98,36.72 33.07,36.72 R28.1
UART1_TX_TGTMCU_R: length 9.7
  TOP w0.152: U8.6 v1(28.21,36.75) 27.67,37.29 27.67,38.71 26.18,40.21 U7.24
V_BATT: length 39.5
  TOP w0.254: R73.2 21.4,20.22 ; R73.2 21.91,19.71 ; R73.2 21.4,19.2
  TOP w0.381: D7.C 16.96,21.01 ; D7.C 15.66,21.9 ; D7.C 15.66,20.12 ; 20.83,17.51 J18.1 21.77,18.45 ; 16.44,19.33 D8.C 17.73,18.44
  TOP w0.635: R72.1 v1(27.62,12.8)
  BOTTOM w0.254: J18.1 TP30.1
  BOTTOM w0.508: J15.3 15.32,11.26 23.16,11.26 24.78,12.88 27.55,12.88 v1(27.62,12.8)
  BOTTOM w0.635: v1(16.27,19.72) 15.58,19.72 13.9,18.05 J15.3 ; R75.2 21.48,20.04 TP30.1
  vias: v1(19.7,20.37)
V_MCU: length 17.8
  INT_1 w0.635: J21.2 24.75,9.45 28.21,9.45 29.1,8.56 J22.2
  BOTTOM w0.254: TP533.1 39.32,8.56 J22.1 J22.2
V_TGTMCU: length 64.8
  TOP w0.305: U14.6 v1(30.21,29.79) ; v1(30.62,40.58) 30.61,40.57 30.61,40.49 30.36,40.24 U5.6 ; U8.8 29.93,35.48 v1(30.16,35.26) ; U16.6 v1(30.39,23.47) ; U13.6 v1(30.11,32.72) ; U15.6 v1(30.26,26.59)
  TOP w0.508: v1(1.74,49.28) 1.74,49.27 R1.1
  INT_1 w0.508: v1(30.39,23.47) 30.26,23.6 v1(30.26,26.59) 30.26,29.74 v1(30.21,29.79) 30.11,29.9 v1(30.11,32.72) 30.11,35.2 v1(30.16,35.26) 30.16,37.13 30.62,37.59 v1(30.62,40.58) ; v1(1.74,49.28) 5.22,49.28 6.06,50.11 v1(7.53,50.11) 8.04,50.11 11.82,46.33 18.3,46.33 19.27,45.36 19.31,45.31 19.33,45.3 21.86,42.77 28.16,42.77 v1(28.79,42.77)
  BOTTOM w0.203: v1(7.53,50.11) 7.22,49.8 U500.8
  BOTTOM w0.254: C503.1 30.62,39.87 v1(30.62,40.58) 30.62,41.63 SH500.1 29.74,41.76 29.74,41.76 29.74,41.83 v1(28.79,42.77)
  BOTTOM w0.508: v1(30.39,23.47) 30.39,23.47 30.39,24.21 C522.1 ; C500.1 7.58,50.06 v1(7.53,50.11) R500.1 ; v1(30.11,32.72) 30.11,32.72 30.11,33.45 30.24,33.58 ; v1(30.21,29.79) 30.21,29.8 30.21,30.53 C517.1 ; C520.1 30.26,27.33 30.26,26.59 v1(30.26,26.59) ; v1(30.16,35.26) C511.1
VDCDC_IN: length 44.5
  TOP w0.279: U18.10 48.67,20.71 48.67,20.24 v1(48.47,20.05)
  TOP w0.381: v1(18.3,24.7) SW5.2
  TOP w0.508: J16.4 28.65,13.57 R72.2
  INT_1 w0.381: J16.4 27.49,14.35 25.9,14.35 25.13,15.11 25.13,18.41 21.8,21.75 19.39,21.75 18.3,22.83 v1(18.3,24.7)
  INT_1 w0.508: 34.95,16.24 J17.4 ; J17.4 36.41,16.24 ; J17.4 36.41,14.78 ; J17.4 34.95,14.78 ; 32.95,16.24 J17.6 ; J17.6 34.41,16.24 ; J17.6 32.95,14.78 ; J17.6 34.41,14.78 ; 29.37,16.24 J16.4 29.37,14.78
  BOTTOM w0.635: v1(48.47,20.05) 47.67,19.25 C531.1 46.62,19.25 46.62,19.25 43.19,19.25 40.37,16.43 v1(39.26,16.43)
VTRG_EN: length 3.6
  TOP w0.152: R41.2 R44.1 12.71,31.06 12.71,32.5 U10.3
VTRG_FAULT_B: length 13.6
  TOP w0.152: v1(17.49,32.51) R33.2 16.66,32.5 U10.4 ; v1(17.49,42.01) 17.72,41.78 U7.32
  INT_1 w0.152: v1(17.49,32.51) 17.49,33.88 18.15,34.54 18.15,40.34 17.72,40.77 17.72,41.78 v1(17.49,42.01)
XTAL_32M: length 5.6
  TOP w0.152: U18.30 54.12,17.4 54.63,16.89 54.63,16.73 56.47,14.89 C41.1 56.47,13.92 56.16,13.61 Y1.3
N20064946: length 26.7
  TOP w0.152: J3.2 27.93,2.57 29.32,1.17 46.72,1.17 48.07,2.51 SH24.2
N20065027: length 3.6
  TOP w0.152: J4.11 61.63,7.01 SH33.2
N20065031: length 3.1
  TOP w0.152: J4.9 61,6.45 60.36,7.08 SH31.2
N20065043: length 2.8
  TOP w0.152: J4.3 SH27.2
N20065047: length 2.8
  TOP w0.152: J4.1 50.86,5.13 SH26.2
N20092069: length 7
  TOP w0.152: J1.16 44.48,49.56 SH10.2 R5.2
N20092076: length 5.7
  TOP w0.152: J1.14 49.56,49.56 SH11.2
N20092083: length 5.7
  TOP w0.152: J1.12 52.1,49.56 SH12.2
N20092090: length 5.7
  TOP w0.152: J1.10 54.64,49.56 SH13.2
N20092097: length 5.7
  TOP w0.152: J1.8 57.28,49.45 SH14.2
N20092104: length 6.1
  TOP w0.152: SH15.2 58.45,46.75 59.5,47.8 59.5,49.77 59.17,50.1 J1.6
N20092111: length 6.1
  TOP w0.152: J1.4 59.86,49.7 59.86,46.63 J31.2
N20092118: length 9.4
  TOP w0.152: J30.1 63.83,43.61 63.94,43.72 63.94,46.27 62.24,47.97 62.24,49.54 J1.2
N20113921: length 7
  TOP w0.152: J2.6 35.39,49.57 35.39,46.18 35.38,46.16 SH7.2 R8.2
N20113927: length 6.6
  TOP w0.152: SH4.2 26.76,45.64 27.76,46.65 27.76,49.56 J2.12
N20113929: length 5.9
  TOP w0.152: J2.8 32.87,49.59 32.87,47.6 32.49,47.22 J28.1
N20113931: length 9
  TOP w0.152: J29.2 30.5,43.62 31.4,43.62 31.49,43.72 31.49,46.53 30.49,47.53 30.49,49.75 J2.10
N20113933: length 7
  TOP w0.152: R3.2 SH8.2 37.92,49.56 J2.4
N20113935: length 7
  TOP w0.152: R4.2 SH9.2 40.46,49.56 J2.2
N20114060: length 6.2
  TOP w0.381: SH3.2 24.71,46.15 24.83,46.15 25.16,46.48 25.16,46.49 25.22,46.55 25.22,49.56 J2.16
N20114116: length 5.4
  TOP w0.152: R87.2 22.68,46.7 22.68,49.56 J2.18
N20184312: length 5.9
  TOP w0.152: SH25.2 49.57,3.84 J4.2
N20184318: length 5.9
  TOP w0.152: SH28.2 54.65,3.84 J4.4
N20184324: length 6.1
  TOP w0.152: J4.6 57.43,4.08 57.43,7.1 57.19,7.34 SH29.2
N20184330: length 6.1
  TOP w0.152: J4.8 59.73,3.84 59.73,6.33 59.09,6.96 SH30.2
N20184336: length 8.5
  TOP w0.152: R45.2 63.28,7.65 63.91,7.02 63.93,7.02 64.88,6.07 64.88,4.74 63.96,3.82 62.25,3.82 J4.10
N20184342: length 7.8
  TOP w0.152: J4.12 65.46,4.48 65.46,8.5 65.27,8.69 65.27,8.71 64.81,9.17 R54.1
N20299169: length 14.1
  TOP w0.292: J6.2 5.17,41.62 5.28,41.72 6.64,41.72 U2.1 7.19,41.15 7.78,41.74 9.61,41.74 v1(10.12,41.2) 10.64,41.74 12.25,41.74 12.76,41.23 12.76,39.16 13.18,38.74 14.13,38.74 14.49,38.38
N20299247: length 14
  TOP w0.292: 14.49,39.55 14.13,39.19 13.37,39.19 13.21,39.34 13.21,41.41 12.44,42.19 10.66,42.19 v1(10.12,42.73) 9.58,42.19 7.79,42.19 7.19,42.79 U1.1 6.58,42.16 5.28,42.16 5.17,42.27 J6.3
N20456851: length 1.3
  TOP w0.152: U4.3 R20.2
N20492386: length 8.4
  TOP w0.152: J2.20 20.01,49.69 20.01,47.58 19.47,47.04 19.33,47.04 18.91,46.62 18.91,45.6 19.83,44.67 19.87,44.67 19.88,44.67 R88.1
N20531142: length 3.7
  TOP w0.152: LED5.C v1(60.41,11.15)
  BOTTOM w0.152: v1(60.41,11.15) TP531.1 R511.1
N20531179: length 2.2
  TOP w0.152: LED6.C v1(14.92,7.39) R81.1
N20532222: length 4.6
  TOP w0.152: R74.2 45.66,12.61 Y2.1 44.47,11.44 43.62,10.59 42.79,10.59 C46.1
N20532224: length 4.5
  TOP w0.152: C47.1 45.02,8.43 Y2.2 47.39,10.81 R77.2
N20553853: length 3
  TOP w0.152: LED4.C TP28.1 R62.1
N20553861: length 3
  TOP w0.152: LED2.C TP25.1 R53.1
N20553879: length 3
  TOP w0.152: LED1.C TP21.1 57.59,29.62 R48.1
N20553881: length 3
  TOP w0.152: R57.1 56.27,26.16 TP26.1 59.21,26.16 LED3.C
N20693809: length 1.8
  TOP w0.152: R68.1 48.12,16.51 U18.18
N20693837: length 6.1
  TOP w0.279: L3.2 46.18,18.95 U18.12
N20693945: length 37.3
  TOP w0.152: U18.47 52.89,24.1 52.89,24.82 v1(52.82,24.88) ; v1(35.25,43.21) 34.79,43.21 34.3,42.72
  INT_1 w0.152: v1(52.82,24.88) 51.58,23.64 50.45,23.64 49.93,24.16 44.67,24.16 44.5,24.32 39.52,24.32 39.1,24.74 39.1,29.65 38.62,30.12 38.62,39.45 36.16,41.9 36.16,42.9 35.86,43.21 v1(35.25,43.21)
N20693947: length 47.9
  TOP w0.152: U18.46 53.04,23.59 53.32,23.87 53.32,25.78 52.95,26.15 52.95,28.11 v1(51.78,29.29) ; R83.1 28.21,45.64 v1(28.69,45.15)
  INT_1 w0.152: v1(51.78,29.29) 50.84,30.23 43.57,30.23 42.96,30.84 42.96,40.97 44.13,42.13 44.13,43.7 42.86,44.96 35.04,44.96 33.39,46.61 29.37,46.61 28.69,45.94 v1(28.69,45.15)
N20694234: length 2.6
  TOP w0.216: 58.56,14.15 58.69,14.27 58.69,14.58 C42.2 R70.2
N20694236: length 2.6
  TOP w0.216: R69.2 C42.1 59.41,15.3 59.71,15.3 Z1.3
N20694515: length 1.9
  TOP w0.152: J16.6 26.64,15.51 R85.1
N20696372: length 2.9
  TOP w0.508: J19.1 D9.A
N20696388: length 6.8
  TOP w0.508: D9.C 16.2,12.4 17.73,13.92 20.54,13.92 20.86,13.59 J23.2
N20696455: length 40.6
  TOP w0.635: J23.1 20.1,11.35 25.16,11.35 J33.1 ; C25.1 v1(4.58,25.15) 2.51,25.15 1.7,24.33 U17.3
  BOTTOM w0.635: J23.1 17.54,12.59 17.53,12.6 TP530.1 15.56,12.6 15.07,13.08 15.07,16.59 17.39,18.9 17.39,20.4 16.34,21.44 8.98,21.44 5.27,25.15 v1(4.58,25.15)
N20743134: length 8.5
  TOP w0.152: Q1.3 v1(51.13,40.66)
  BOTTOM w0.152: v1(51.13,40.66) 52.33,40.66 R512.2 52.37,40.66 52.96,40.66 53.81,41.52 55.37,41.52 56.23,40.66 BZ500.2
N20743140: length 3.5
  TOP w0.152: Q1.1 48.94,42.67 R14.1 45.49,42.68 R12.2
N20743144: length 24.3
  INT_1 w0.152: v1(52.33,30.36) 52.85,30.36 53.61,31.12 53.61,32.51 52.24,33.88 52.24,34.57 52.24,40.8 v1(53.1,41.67)
  BOTTOM w0.152: v1(53.1,41.67) 53.08,41.67 53.05,41.7 R512.1 ; v1(52.33,30.36) 52.33,28.57 51.98,28.22 TP526.1
  BOTTOM w0.381: BZ500.1 54.7,27.66 54.59,27.55 52.06,27.55 TP526.1 R507.2
N20744082: length 2.7
  TOP w0.508: R82.2 v1(24.04,2.67) 24.04,0.97 D11.A
N20744086: length 3.3
  TOP w0.152: Q2.1 21.73,3.99 v1(21.86,3.86)
  BOTTOM w0.152: R79.1 21.35,4.37 v1(21.86,3.86) 22.36,4.37 R80.2
N20744096: length 2.3
  TOP w0.152: D11.C 20.71,0.94 v1(20.71,2.08) Q2.3
N20748907: length 14.9
  BOTTOM w0.254: R67.1 6.86,13.88 11.15,13.88 12.53,12.5 12.53,9.32 13.09,8.76 14.82,8.76 J15.2
N20755274: length 2.5
  TOP w0.152: U12.5 42.35,30.23 v1(42.61,29.97) 43.57,29.01
N20755276: length 2.1
  TOP w0.152: 41.03,29.01 41.35,29.32 v1(41.35,30) U12.3
N20755278: length 2.2
  TOP w0.152: 42.3,29.01 41.85,29.46 U12.4
N20755280: length 2.7
  TOP w0.152: SH23.1 39.74,29.63 v1(40.12,30.02) 40.5,30.02 40.85,30.37 U12.2
N20771285: length 7.7
  BOTTOM w0.635: J23.3 20.1,15.35 20.1,17.98 20.38,18.26 R75.1
N20771753: length 9.9
  TOP w0.508: R73.1 19.19,19.71 18.99,19.51 D8.A 18.99,16.98 18.64,16.64 J27.1
  BOTTOM w0.635: TP29.1 18.64,18.83 J27.1
N20845596: length 1.5
  TOP w0.152: R22.1 43.6,38.51 U4.5
N20885985: length 23
  TOP w0.254: L2.1 4.99,37.01 ; L2.1 4.49,37.61 ; L2.1 4.99,37.61 ; L2.1 4,37.01
  TOP w0.381: 1.44,45.3 J6.9 ; 3.53,40.04 J6.7 ; J6.8 1.44,43.92 ; J6.8 1.44,40.61 ; J6.8 2.58,42.27 ; J6.8 2.58,43.92 ; 3.53,44.49 J6.6 ; 1.44,37.28 J6.10
  BOTTOM w0.152: 3.61,40.04 J6.7 ; J6.7 4.44,40.76 ; J6.7 4.44,39.32 ; 1.44,37.35 J6.10 ; J6.10 1.44,39.16 ; J6.10 2.58,38.18 ; 4.44,43.77 J6.6 ; J6.6 3.61,44.49 ; J6.6 4.44,45.22 ; J6.9 2.58,46.36 ; J6.9 1.44,45.37 ; J6.9 1.44,47.18
  vias: v1(2.9,44.52) v1(2.87,39.98) v1(3.47,37.08)

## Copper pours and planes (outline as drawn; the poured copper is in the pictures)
GND on GND (solid shape): outline of 98 points within 62.93,27.48 66.46,31.09
GND on GND (solid shape): outline of 99 points within 62.93,21.31 66.46,24.92
GND on TOP: 23.13,37.36 23.13,36.42 23.58,35.97 27.47,35.97 27.47,37.69 23.46,37.69
GND on TOP: 51.96,15.94 47.91,19.99 51.81,23.88 55.85,19.84 ; 3 cut-outs
GND on TOP: 42.2,8.59 43.3,7.49 43.62,7.49 43.62,7.48 47.46,11.33 47.46,12.29 47.13,12.62 46.01,12.62 42.2,8.81
GND on TOP: 54.88,15.93 55.38,15.93 57.04,14.27 57.04,10.62 56.71,10.29 53.43,10.29 53.1,10.62 53.1,14.15
GND on TOP: 6.35,0.38 2.13,2.13 0.38,6.35 0.38,46.99 2.13,51.21 6.35,52.96 74.93,52.96 79.15,51.21 80.9,46.99 80.91,39.38 73.14,39.38 73.14,0.38 ; 38 cut-outs
GND on BOTTOM, GND: 0.38,46.99 2.13,51.21 6.35,52.96 74.93,52.96 79.15,51.21 80.9,46.99 80.91,39.38 73.14,39.38 73.14,0.38 6.35,0.38 2.13,2.13 0.38,6.35
GND on INT_1: 0.38,46.99 2.13,51.21 6.35,52.96 74.93,52.96 79.15,51.21 80.9,46.99 80.91,39.38 73.14,39.38 73.14,0.38 6.35,0.38 2.13,2.13 0.38,6.35 ; 24 cut-outs
P3V3 on TOP: 23.66,11.65 23.66,17.01 23.06,17.01 23.06,20.96 26.2,20.96 27.06,20.09 31.43,20.09 32.4,19.13 32.4,7.95 39.38,7.95 39.38,2.06 26.96,2.06 26.53,2.49 26.53,8.05 24.88,9.7 11.72,9.7 10.63,10.79 5.09,10.79 4.81,11.07 3.59,11.07 2.43,12.24 0.37,12.24 0.37,15.06 7.91,15.06 8.93,14.05 14.59,14.05 15.18,13.46 15.18,11.84 15.36,11.65
P3V3_BATT on TOP: 8.18,19.46 11.65,19.46 11.65,17.93 12.76,16.81 18.05,16.81 18.05,14.2 9.08,14.2 8.18,15.1
P3V3_VREG on TOP: 3.04,24.36 5.25,24.36 5.25,22.19 14.08,22.19 14.08,19.81 6.36,19.81 6.36,15.44 1.58,15.44 1.58,20.78 3.04,20.78
P5V_LDO_OUT on TOP: 6.39,6.81 6.39,5.38 5.12,4.11 5.12,2.26 2.88,2.26 2.81,2.34 2.81,4.83 1.67,4.83 1.22,5.28 1.22,6.64 1.38,6.81
P5V_SDA on TOP: 11.21,39.8 11.49,39.8 12.94,38.35 12.94,34.16 12.89,34.11 10.81,34.11 10.81,31.5 10.91,31.39 12.03,31.39 12.03,30.3 11.95,30.23 10.02,30.23 10.02,35.26 10.05,35.28 11.54,35.28 11.54,38.23 11.19,38.58 11.19,39.78
P5V_USB on TOP: 4.28,32.89 7.61,32.89 7.61,30.15 4.31,30.15 4.25,30.2 4.25,32.87
VDD_1P45F on BOTTOM: 53.03,17.62 55.08,19.67 54.33,20.42 52.48,18.58 52.48,18.17
P5-9V_VIN on TOP: 6.95,6.5 12.51,6.5 12.51,5.51 10.99,3.99 10.99,2.31 10.96,2.29 8.22,2.29 8.22,4.29 6.95,5.56
P5-9V_VIN_VR on TOP: 0.39,35.59 3.47,35.59 3.47,25.93 2.81,25.27 2.81,24.84 0.39,24.84
RF_ANT on TOP (solid shape): 74.42,14.09 73.56,14.09 72.11,14.28 72.11,14.74 73.56,14.94 74.42,14.94
V_BATT on TOP: 22.16,17.17 22.14,17.15 20.28,17.15 20.28,18.16 17.26,18.16 17.26,18.15 15.43,18.15 15.43,22.68 22.16,22.68
VDCDC_IN on INT_1: 28.21,16.74 39.2,16.74 40.04,15.9 40.04,14.35 28.31,14.35 28.23,14.27 28.21,14.3
N20885985 on TOP (solid shape): 2.39,46.51 5.06,46.51 5.06,44.49 3.81,44.49 3.81,45.49 0.48,45.49 0.48,47.22 2.39,47.22
N20885985 on TOP (solid shape): 5.06,38.02 2.39,38.02 2.39,37.31 0.48,37.31 0.48,39.04 3.81,39.04 3.81,40.04 5.06,40.04
N20885985 on TOP: 5.11,47.68 5.11,36.55 0.48,36.55 0.48,47.68
N20885985 on BOTTOM: 4.86,45.14 4.86,36.55 0.39,36.55 0.39,47.68 2.32,47.68

Small or netless copper shapes (teardrops, artwork), in the pictures only: 2 on TOP

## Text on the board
BOTTOM: 170-28379 REV C | 7 OF 10 | SECONDARY SIDE
Ref Des/Assembly Bottom: 2 OF 2 | SECONDARY ASSEMBLY
Ref Des/Silkscreen Bottom: SCH-28370_C | 700-28379_C | 5V EXT GEN | RF | I2C0 | P3V3 | GND | SPI0 | P5V | P5-9V | UART0 | OpenSDA | 10 OF 10 | SECONDARY SILKSCREEN | FCC ID XZZYYNNNNN | XXX-XXXXX | R
User.Comments: 8 OF 10 | SECONDARY SOLDERMASK | 1 OF 1 | TEST PROBE | 1/1 | 1
TOP: 4 OF 10 | PRIMARY SIDE
Ref Des/Assembly Top: 1 OF 2 | PRIMARY ASSEMBLY
Board Geometry/Soldermask Top: 3 OF 10 | PRIMARY SOLDERMASK
Ref Des/Silkscreen Top: OUT | IN | SMA | SDA | GND | MKW40Z | COM | F-ANTENNA | PWR | RST | PSWITCH | SWD | 1 OF 10 | PRIMARY SILKSCREEN | FRDM-KW40Z | +
GND: 5 OF 10 | L2_GND
INT_1: 6 OF 10 | L3_INT_1
DIMENSION: GRID ORIGIN | PRIMARY DATUM
BODY_CENTER: A - TARGET : 10 MILS | B - TARGET : 38 MILS | C - TARGET : 10 MILS | TRACE: 8.5 MILS WIDTH | SPACING: 6 MILS | 100 OHMS DIFF PAIR | 50 OHMS SINGLE ENDED | TRACE: 18 MILS +/-10% | SH3 P3V3 & N20114060 | SH4 SPI_CLK & N20113927: | SH7 SPI_SS & N20113921 | SH8 KW40_SWD_CLK & N20113933 | SH9 SWD_DIO_TGTMCU & N20113935 | SH10 BUZZER & N20092069 | SH11 INT1_COMBO & N20092076 | SH12 SW3 & N20092083 | SH13 SW4 & N20092090 | SH14 ELEC_IN2 & N20092097 | SH15 ELEC_IN1 & N20092104 | SH18 SA1_FXOS8700CQ | SH19 SA0_FXOS8700CQ | J12 SWD_CLK_TGTMCU & KW40_SWD_CLK | J13 SWD_DIO_TGTMCU_BUF & SWD_DIO_TGTMCU | J14 SWD_CLK_TGTMCU_BUF & SWD_CLK_TGTMCU | J25 SDA_RST_TGTMCU_J_B & SDA_RST_TGTMCU_B | SH21 SWD_DIO_TGTMCU & N20755278 | SH22 BUZZER & N20755274 | SH23 PTC5 & N20755280 | SH24 PTC4 & N20064946 | SH25 PTB17 & N20184312 | SH26 ADC0_SE0/BATTERY_MONITORING & N20065047 | SH27 ADC0_SE1/POT & N20065043 | SH28 PTB16 & N20184318 | SH29 CMT & N20184324 | SH30 PTC5 & N20184330 | SH31 COM & N20065031 | SH33 PTB18 & N20065027 | SH500 V_TGTMCU & P3V3 | SH501 P3V3_SDA & SDA_VOUT33 | SH502 P3V3 & SDA_VOUT33 | SH503 P3V3_LED & P3V3 | 23. INTENTIONAL SHORT ON TOP LAYER BETWEEN RF_ANT AND GND | 24. OVERALL PCB DIELECTRIC THICKNESS ARE TARGETED (A & C) 10 MILS+/-10% AND (B) 38 MILS +/-10% | 22. INTENTIONAL SHORTS AT: | AS SHOWN IN DETAIL 'A'. ADJUSTEMENT IN SUBSTRATE B IS ALLOWED TO MEET OVERALL HEIGHT REQUIREMENT. | Er - MUST BE FROM 4.2 TO 4.4 | 24 | 16 | 23 | 17 | 8 | DETAIL B
DISPLAY_TOP: 2 OF 10 | PASTEMASK TOP
User.5: 9 OF 10 | SECONDARY PASTEMASK
User.14: 12-02-14 | 07/31/15 | 07-04-14 | 11-12-14 | A.Q | B2 | C | B | B1 | UPDATE SHORT LIST | Respin | RE-SPIN PER ECO
User.17: Trace Width | (Mils) | Trace Spacing | "Airgap" | Impedance | (Ohms) | 8.50 | 6.00 | 100 | Differential
User.20: FIGURE | SIZE | 8.0 | 10.0 | 12.0 | 28.0 | 35.0 | 40.0 | 42.0 | 63.0 | 73.0 | 125.0 | 34.0x26.0 | 60.0x33.0 | DRILL CHART: TOP to BOTTOM | ALL UNITS ARE IN MILS | TOLERANCE | +0.0/-8.0 | +0.0/-10.0 | +0.0/-12.0 | +2.0/-2.0 | +3.0/-3.0 | PLATED | NON-PLATED | QTY | 284 | 564 | 2 | 20 | 57 | 8 | 64 | 1 | 4
